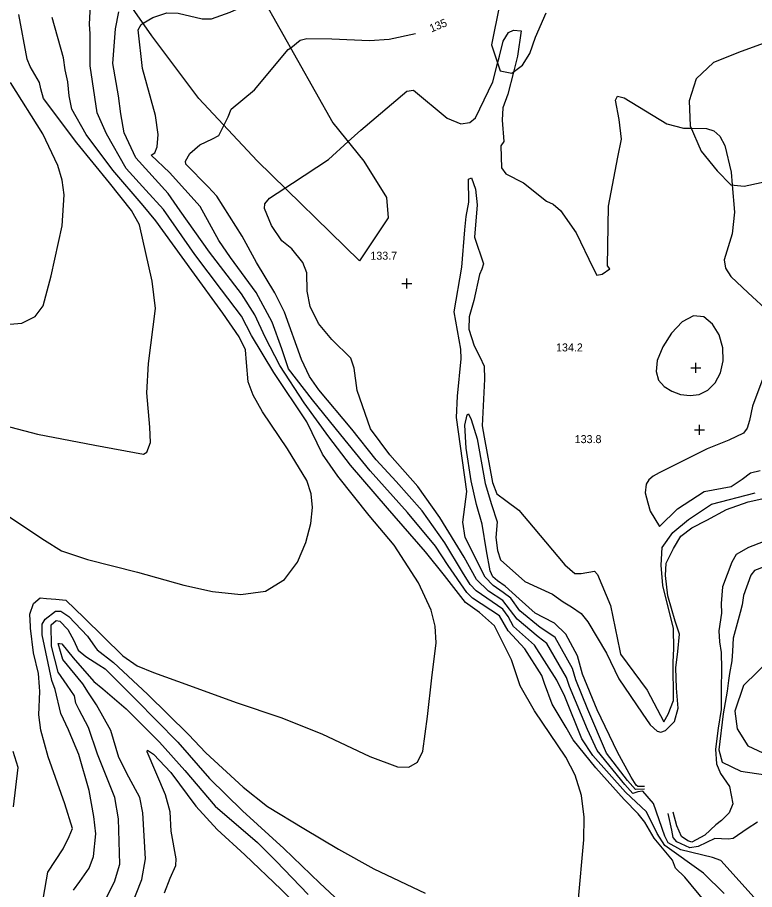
# Model space of a CAD drawing. Extents: x 1475150 to 2003689, y 770235 to 1112803.
# Drawn here: x 2000830.5 to 2001014.7, y 773169.6 to 773387.6 of the extents above; entities that cross this region are included whole.
import ezdxf

# ---------------------------------------------------------------- set-up
doc = ezdxf.new("R2010")
doc.units = 0
for name, color, linetype in [('RD_DTM_Major1', 7, 'Continuous'), ('RD_DTM_Major1_Lbl', 7, 'Continuous'), ('RD_DTM_Major2', 7, 'Continuous'), ('RD_DTM_Minor1', 7, 'Continuous'), ('RD_DTM_Minor2', 7, 'Continuous'), ('RD_DTM_Obscure', 7, 'Continuous'), ('RD_DTM_Spot_Elev', 7, 'Continuous')]:
    doc.layers.add(name, color=color, linetype=linetype)

msp = doc.modelspace()

# ---------------------------------------------------------------- linework, layer by layer
at = {"layer": 'RD_DTM_Major1'}
for points in [[(2000823.61, 773286.56), (2000835.44, 773283.45), (2000849.78, 773280.65), (2000861.94, 773278.4), (2000862.84, 773278.97), (2000863.74, 773281.34), (2000863.57, 773285.19), (2000862.8, 773293.75), (2000863.21, 773301.08), (2000864.95, 773314.89), (2000864.13, 773321.67), (2000861.01, 773335.77), (2000858.98, 773339.39), (2000853.45, 773346.24), (2000845.35, 773356.26), (2000837.01, 773367.33), (2000836.27, 773369.74), (2000836, 773371.36), (2000833.61, 773375.31), (2000832.9, 773377.17), (2000830.83, 773388.35)], [(2000898.77, 773380.04), (2000901.12, 773381.94), (2000902.79, 773382.31), (2000909.07, 773382.25), (2000918.51, 773381.88), (2000923.39, 773382.14), (2000929.97, 773383.62)], [(2001007.11, 773168.58), (2001001.96, 773173.74), (2000992.33, 773180.61), (2000990.39, 773183.64), (2000987.75, 773189.06), (2000982.44, 773193.96), (2000974.3, 773203.14), (2000971.57, 773207.31), (2000967.29, 773217.86), (2000965.29, 773221.91), (2000959.7, 773230.67), (2000954.49, 773235.36), (2000953.17, 773237.9), (2000951.82, 773239.71), (2000945.11, 773244.26), (2000943.67, 773245.83), (2000941.74, 773248.92), (2000937.29, 773256.3), (2000931.61, 773264.29), (2000925.11, 773271.64), (2000920.11, 773277.05), (2000914.03, 773284.7), (2000905.83, 773294.52), (2000903.5, 773297.85), (2000901.49, 773302.08), (2000897.23, 773313.94), (2000894.85, 773318.79), (2000890.21, 773326.36), (2000886.63, 773332.92), (2000880.33, 773342.97), (2000878.17, 773345.3), (2000872.59, 773350.92), (2000872.47, 773351.65), (2000873.6, 773353.57), (2000876.03, 773355.75), (2000879.2, 773357.29), (2000880.82, 773358.06), (2000882.1, 773360.61)], [(2000858.92, 773165.4), (2000861.54, 773172.12), (2000862.46, 773177.26), (2000861.8, 773188.76), (2000861.02, 773192.62), (2000858.28, 773197.67), (2000855.8, 773202.65), (2000853.78, 773209.38), (2000850.21, 773215.8), (2000848.25, 773218.77), (2000846.78, 773220.99), (2000841.81, 773227.11), (2000840.62, 773231.12), (2000840.96, 773231.09), (2000841.55, 773231.06), (2000844.37, 773227.53), (2000849.57, 773221.61), (2000851.85, 773219.77), (2000857.63, 773214.81), (2000866, 773206.47), (2000872.28, 773199.4), (2000879.86, 773190.48), (2000890.44, 773181.38), (2000895.17, 773176.72), (2000903.11, 773168.36)]]:
    msp.add_lwpolyline(points, dxfattribs=at)
at = {"layer": 'RD_DTM_Major2'}
msp.add_lwpolyline([(2000882.1, 773360.61), (2000883.18, 773362.75), (2000883.92, 773364.66), (2000889.7, 773369.5), (2000898.18, 773379.57), (2000898.77, 773380.04)], dxfattribs=at)
at = {"layer": 'RD_DTM_Minor1'}
for points in [[(2000835.89, 773161.45), (2000838.06, 773173.95), (2000841.91, 773179.77), (2000843.41, 773182.86), (2000844.21, 773184.91), (2000842.31, 773191), (2000838.17, 773202.81), (2000836.27, 773209.45), (2000835.8, 773213.25), (2000836.04, 773219.12), (2000835.96, 773220.31), (2000835.73, 773223.6), (2000834.51, 773228.8), (2000833.74, 773234.97), (2000833.69, 773235.38), (2000833.56, 773238.41), (2000834.49, 773241.12), (2000836.15, 773242.55), (2000837.71, 773242.37), (2000840.08, 773242.22), (2000842.54, 773241.91), (2000847.17, 773237.56), (2000856.82, 773228.02), (2000860.37, 773225.57), (2000864.47, 773223.86), (2000873.44, 773220.6), (2000885.12, 773216.39), (2000896.32, 773212.63), (2000906.6, 773208.57), (2000918.52, 773202.83), (2000925.47, 773200.25), (2000928.34, 773200.18), (2000930.5, 773201.42), (2000931.83, 773204.2), (2000932.96, 773212.87), (2000934.05, 773222.5), (2000935.12, 773231.27), (2000934.92, 773235.42), (2000933.92, 773239.43), (2000930.7, 773246.29), (2000924.64, 773255.67), (2000918.42, 773263.14), (2000910.57, 773272.92), (2000906.73, 773278.42), (2000902.84, 773286.5), (2000894.59, 773298.83), (2000888.95, 773308.13), (2000886.48, 773312.92), (2000881.5, 773319.56), (2000874.82, 773328.37), (2000866.95, 773339.58), (2000862.6, 773344.42), (2000857.65, 773349.82), (2000852.7, 773358.52), (2000850.42, 773363.76), (2000848.61, 773375.52), (2000848.65, 773383.49), (2000848.47, 773385.92), (2000848.73, 773390.67)], [(2000826.59, 773264.05), (2000837.22, 773256.95), (2000841.51, 773254.25), (2000848.01, 773252.15), (2000860.47, 773248.98), (2000872.06, 773245.73), (2000879.22, 773244.11), (2000886.3, 773243.38), (2000892.51, 773244.22), (2000897.21, 773247.09), (2000900.49, 773251.41), (2000902.59, 773256.36), (2000903.77, 773261.14), (2000904.22, 773265.12), (2000903.92, 773268.55), (2000902.81, 773271.87), (2000898.01, 773279.81), (2000891.74, 773289.06), (2000889.38, 773293.2), (2000888.12, 773296.56), (2000887.71, 773301.32), (2000887.5, 773304.54), (2000885.86, 773307.75), (2000881.85, 773313.71), (2000874.05, 773324.35), (2000865.09, 773336.78), (2000861.91, 773340.56), (2000854.3, 773349.44), (2000847.65, 773358.36), (2000844.1, 773364.68), (2000843.39, 773368.05), (2000843.07, 773371.53), (2000842.38, 773374.53), (2000841.94, 773377.53), (2000839.16, 773387.63)], [(2000970.62, 773166.4), (2000972.09, 773182.07), (2000972.16, 773187.7), (2000971.49, 773193.14), (2000969.86, 773198.17), (2000967.57, 773202.69), (2000959.7, 773214.29), (2000956.14, 773220.49), (2000953.98, 773227.07), (2000949.72, 773235.53), (2000945.98, 773238.9), (2000942.51, 773241.37), (2000937.22, 773248.09), (2000932.51, 773254.05), (2000923, 773264.92), (2000913.71, 773275.65), (2000908.27, 773282.81), (2000902.16, 773291.29), (2000896.09, 773300.57), (2000892.43, 773307.72), (2000889.83, 773313.3), (2000886.51, 773318.51), (2000878.51, 773328.92), (2000871.17, 773339.24), (2000868.13, 773343.6), (2000860.07, 773352.52), (2000857.17, 773358.73), (2000856.34, 773363.48), (2000855.73, 773368.01), (2000854.28, 773376.12), (2000854.97, 773384.73), (2000855.81, 773389.03)], [(2001007.61, 773160.19), (2000997.3, 773172.67), (2000994.95, 773174.96), (2000994.19, 773176.99), (2000989.63, 773182.48), (2000987.31, 773186.44), (2000985.66, 773188.52), (2000982.13, 773192.14), (2000975.07, 773200.04), (2000969.35, 773207.06), (2000967.6, 773210.12), (2000964.17, 773215.91), (2000962.26, 773221.09), (2000961.53, 773223.14), (2000957.27, 773229.81), (2000953.1, 773234.27), (2000951.01, 773238.07), (2000944.2, 773242.45), (2000942.82, 773243.9), (2000938.16, 773250.64), (2000934.94, 773255.43), (2000928.01, 773263.88), (2000918.62, 773274.26), (2000911.31, 773283.26), (2000904.24, 773292.01), (2000898.25, 773299.77), (2000896.58, 773304.78), (2000894.12, 773311.43), (2000890.11, 773318.89), (2000883.75, 773327.64), (2000880.83, 773331.83), (2000876.14, 773340.37), (2000868.44, 773348.87), (2000863.92, 773353.17), (2000864.79, 773353.74), (2000865.43, 773355.3), (2000865.67, 773358.37), (2000864.94, 773363.06), (2000861.7, 773374.85), (2000860.62, 773384.49), (2000861.41, 773385.87), (2000861.92, 773386.16)], [(2000913.14, 773356.58), (2000916.29, 773359.44), (2000927.84, 773369.15), (2000929.46, 773369.45), (2000937.86, 773362.44), (2000941.29, 773360.98), (2000943.55, 773361.32), (2000944.99, 773362.54), (2000949.32, 773371.55), (2000950.51, 773376.09)], [(2000954.44, 773373.93), (2000953.04, 773368.43), (2000951.84, 773364.99), (2000951.68, 773361.9), (2000952.02, 773356.56), (2000951.31, 773355.48), (2000951.46, 773350.01), (2000952.54, 773348.51), (2000956.98, 773346.3), (2000962.7, 773341.69), (2000964.38, 773340.93), (2000966.24, 773339.38), (2000970.1, 773333.74), (2000974.4, 773324.95), (2000975.32, 773323.19), (2000976.63, 773323.42), (2000978.53, 773324.77), (2000977.99, 773325.52), (2000978.22, 773340.42), (2000980.53, 773352.66), (2000981.49, 773357.22), (2000980.87, 773362.1), (2000979.95, 773366.89), (2000980.48, 773367.94), (2000982.13, 773367.54), (2000992.83, 773361.02), (2000996.94, 773359.95), (2000998.9, 773359.93)], [(2000826.59, 773310.79), (2000831.54, 773311.18), (2000834.86, 773312.82), (2000836.86, 773315.53), (2000838.91, 773322.98), (2000841.64, 773335.52), (2000842.13, 773343.3), (2000841.61, 773346.95), (2000840.56, 773350.62), (2000836.82, 773358.51), (2000828.75, 773371.32)], [(2000987.21, 773194.73), (2000984.99, 773194.59), (2000982.96, 773196.88), (2000977.74, 773203.73), (2000973.07, 773214.58), (2000970.08, 773222.05), (2000969.19, 773224.9), (2000964.89, 773232.62), (2000963.3, 773233.72), (2000961.14, 773235.13), (2000956.03, 773239.25), (2000953.77, 773242.44), (2000951.85, 773243.88), (2000949.39, 773245.57), (2000947.42, 773247.72), (2000942.41, 773257.59), (2000941.79, 773261.43), (2000942.78, 773269.14), (2000941.74, 773276.88), (2000940.21, 773287.64), (2000940.47, 773292.95), (2000941.4, 773302.27), (2000941.28, 773304.71), (2000939.68, 773314), (2000941.56, 773325.16), (2000942.27, 773334.55), (2000942.61, 773337.83), (2000943.31, 773341.45), (2000943.26, 773347.15), (2000944.01, 773347.51), (2000944.96, 773344.66), (2000945.39, 773340.77), (2000944.69, 773332.69), (2000946.98, 773326.02), (2000946.57, 773324.68), (2000945.96, 773323.36), (2000944.56, 773316.89), (2000943.36, 773312.79), (2000943.34, 773309.72), (2000944.65, 773305.51), (2000946.08, 773302.79), (2000947.18, 773300.41), (2000947.23, 773297.18), (2000946.65, 773285.56), (2000947.18, 773282.73), (2000949.2, 773271.35), (2000950.32, 773268.54), (2000952.57, 773266.9), (2000955.8, 773264.47), (2000959.41, 773260.2), (2000967.3, 773250.79), (2000969.79, 773248.63), (2000971.42, 773248.61), (2000974.69, 773249.2), (2000975.48, 773248.35), (2000978.69, 773240.64), (2000981.02, 773229.29), (2000981.2, 773228.48), (2000987.88, 773219.42), (2000992.05, 773211.51), (2000993.18, 773213.49), (2000994.48, 773216.86), (2000994.35, 773226.53), (2000994.59, 773229.81), (2000994.49, 773234.83), (2000991.77, 773245.59), (2000991.35, 773250.72), (2000991.68, 773255.12), (2000994.29, 773258.89), (2000998.25, 773262.15), (2001003.94, 773265.92), (2001014.9, 773268.8)], [(2001014.65, 773167.6), (2001006.28, 773176.87), (2001004.23, 773177.61), (2000996.28, 773179.53), (2000993.12, 773181.3), (2000992.34, 773182.97), (2000989.5, 773191.09), (2000986.82, 773194.24), (2000985.55, 773194.02), (2000984.29, 773193.61), (2000982.29, 773195.84), (2000975.38, 773204.38), (2000972.94, 773209.6), (2000968.49, 773220.37), (2000967.69, 773222.63), (2000962.79, 773231.08), (2000960.6, 773232.8), (2000955.37, 773237.19), (2000951.77, 773241.85), (2000948.24, 773244.16), (2000945.26, 773247.09), (2000942.16, 773252.73), (2000936.05, 773262.58), (2000930.59, 773270.37), (2000923.58, 773278.27), (2000918.71, 773284.74), (2000915.43, 773294.39), (2000914.66, 773299.94), (2000913.77, 773302.46), (2000909.03, 773307.11), (2000905.72, 773311.07), (2000903.64, 773315.34), (2000902.93, 773319.18), (2000902.84, 773323.76), (2000901.8, 773326.36), (2000899.07, 773329.76), (2000896.57, 773331.77), (2000893.96, 773335.62), (2000892.2, 773339.86), (2000892.29, 773340.98), (2000893.51, 773342.43), (2000897.35, 773344.97)], [(2001009.15, 773345.73), (2001009.75, 773338.9), (2001009.13, 773333.54), (2001007.14, 773326.98), (2001007.46, 773324.93), (2001008.77, 773322.83), (2001013.1, 773318.77), (2001018.38, 773313.94)], [(2001003.07, 773294.42), (2001004.87, 773296.28), (2001006.19, 773298.8), (2001006.89, 773301.79), (2001006.82, 773305.01), (2001005.91, 773308.23), (2001004.26, 773310.97), (2001002.05, 773312.74), (2000999.45, 773313.02), (2000996.65, 773311.51), (2000993.98, 773308.7), (2000991.77, 773305.25), (2000990.4, 773301.86), (2000990.1, 773299.08), (2000990.75, 773296.93), (2000992.14, 773295.33), (2000994.05, 773294.16), (2000996.26, 773293.38), (2000998.6, 773293.07), (2001000.93, 773293.37), (2001003.07, 773294.42)], [(2001017.04, 773298.06), (2001014.25, 773290.44), (2001013.46, 773286.87), (2001012.92, 773284.91), (2001011.99, 773283.67), (2001008.27, 773281.96), (2001002.85, 773279.77), (2000990.89, 773273.75), (2000989.38, 773272.98), (2000988.3, 773272.05), (2000987.68, 773270.97), (2000987.42, 773268.81), (2000988.03, 773266.26), (2000988.64, 773264.17), (2000991, 773260.32), (2000995.45, 773264.77), (2001002.1, 773269.13), (2001008.85, 773270.34), (2001011.68, 773272.21), (2001013.69, 773273.76), (2001016.17, 773274.38)], [(2000987.19, 773195.4), (2000985.52, 773195.35), (2000985.12, 773195.68), (2000983.88, 773197.74), (2000980.49, 773203.91), (2000975.4, 773214.55), (2000971.74, 773223.48), (2000970.46, 773228.05), (2000967.52, 773233.47), (2000964.7, 773236.2), (2000961.94, 773237.59), (2000959.92, 773238.7), (2000955.93, 773242.29), (2000952.37, 773245.42), (2000950.51, 773246.81), (2000949.27, 773247.74), (2000948.65, 773249.29), (2000947.72, 773254.24), (2000946.64, 773260.93), (2000945.25, 773265.86), (2000943.85, 773271.74), (2000942.61, 773279.95), (2000942.3, 773285.68), (2000942.85, 773288.29), (2000943.25, 773288.56), (2000943.85, 773287.07), (2000945.4, 773282.27), (2000947.41, 773271.12), (2000948.96, 773265.86), (2000950.36, 773261.52), (2000950.05, 773257.65), (2000950.51, 773254.4), (2000951.23, 773252.01), (2000957.27, 773246.61), (2000960.38, 773245.18), (2000964.2, 773243.48), (2000965.72, 773242.33), (2000966.89, 773241.51), (2000968.99, 773240.3), (2000971.35, 773238.59), (2000973.03, 773236.56), (2000977.71, 773228.71), (2000980.79, 773222.28), (2000986.64, 773213.73), (2000988.68, 773210.82), (2000990.39, 773209.23), (2000991.34, 773208.96), (2000992.48, 773209.38), (2000994.76, 773211.62), (2000995.67, 773214.94), (2000995.24, 773219.93), (2000995.02, 773224.99), (2000995.52, 773229.13), (2000995.95, 773233.48), (2000994.88, 773236.69), (2000993.03, 773243.03), (2000992.46, 773248.1), (2000992.67, 773251.16), (2000994.45, 773254.87), (2000996.31, 773257.94), (2000999.09, 773260), (2001002.8, 773261.93), (2001007.72, 773264.64), (2001013.14, 773266.49), (2001020.27, 773268.13)], [(2001016.92, 773256.51), (2001013.23, 773255.09), (2001010.15, 773253.34), (2001009.03, 773251.44), (2001006.7, 773245.29), (2001006.43, 773241.15), (2001006.51, 773238.68), (2001005.83, 773234.32), (2001006, 773231.56), (2001006.38, 773228.83), (2001006.48, 773224.82), (2001006.43, 773219.64), (2001006.36, 773214.58), (2001005.65, 773209.95), (2001004.94, 773204.74), (2001005.22, 773201.03), (2001006.22, 773198.61), (2001008.51, 773195.39), (2001009.32, 773191.07), (2001008.37, 773188.77), (2001006.46, 773186.86), (2001005.08, 773185.78), (2001002.28, 773183.2), (2000999.09, 773181.48), (2000998.09, 773181.75), (2000996.46, 773182.91), (2000995.3, 773185.55), (2000994.43, 773188.94)], [(2001021.96, 773252.11), (2001014.7, 773249.39), (2001013.83, 773248.2), (2001011.98, 773243.1), (2001011.6, 773240.8), (2001011.13, 773238.88), (2001009.37, 773232.44), (2001009.22, 773229.23), (2001009.04, 773226.79), (2001008.44, 773223.61), (2001008.24, 773221.9), (2001007.91, 773219.16), (2001006.86, 773213.56), (2001005.81, 773204.57), (2001006.65, 773201.41), (2001011.33, 773199.17), (2001017.49, 773198.26)], [(2000844.49, 773169.47), (2000846.02, 773171.61), (2000848.39, 773174.92), (2000849.5, 773177.9), (2000850.09, 773183.55), (2000849.54, 773187.89), (2000848.39, 773194.33), (2000845.8, 773203.35), (2000843.4, 773209.1), (2000843.2, 773209.54), (2000841.29, 773213.62), (2000839.92, 773219.59), (2000839.05, 773221.85), (2000836.65, 773233.26), (2000836.67, 773235.94), (2000837.4, 773237.18), (2000839.99, 773239.17), (2000841.3, 773239.23), (2000843.32, 773237.84), (2000848, 773232.94), (2000849.92, 773230.2), (2000850.37, 773229.57), (2000854.49, 773226.36), (2000862.97, 773218.48), (2000873.19, 773208.36), (2000877.54, 773203.81), (2000886.86, 773195.18), (2000892.94, 773190.35), (2000902.03, 773184.9), (2000910.71, 773179.67), (2000919.52, 773174.8), (2000932.39, 773168.72)], [(2000851.53, 773165.3), (2000854.72, 773171.56), (2000856.05, 773175.92), (2000855.74, 773187.25), (2000854.77, 773192.6), (2000850.51, 773203.48), (2000848.22, 773210.1), (2000845.93, 773214.52), (2000845.05, 773216.22), (2000844.76, 773218.07), (2000842.92, 773220.67), (2000840.65, 773223.98), (2000839, 773230.41), (2000838.92, 773235.8), (2000840.15, 773236.86), (2000841.04, 773236.68), (2000843.08, 773234.61), (2000844.6, 773231.9), (2000845.63, 773229.48), (2000847.56, 773227.85), (2000850.82, 773225.8), (2000852.39, 773224.81), (2000860.03, 773217.11), (2000870.54, 773206.41), (2000878.44, 773197.34), (2000886.72, 773189.25), (2000897.04, 773179.9), (2000906.02, 773171.21), (2000914.71, 773163.12)], [(2000867.25, 773168.77), (2000868.66, 773172.43), (2000870.09, 773175.59), (2000870.18, 773177.32), (2000868.86, 773184.2), (2000868.61, 773189.03), (2000867.48, 773193.25), (2000862.92, 773204.07), (2000863.01, 773204.46), (2000864.51, 773203.43), (2000868.78, 773198.83), (2000875.1, 773190.49), (2000880.36, 773184.66), (2000887.33, 773178.25), (2000896.37, 773169.65), (2000906.34, 773159.89)], [(2000829.44, 773190.32), (2000830.68, 773200.15), (2000829.38, 773204.12)], [(2001015.47, 773186.48), (2001012.89, 773184.8), (2001009.42, 773182.37), (2001008.17, 773182.17), (2001004.83, 773182.38), (2001002.75, 773181.38), (2001000.67, 773180.38), (2000998.57, 773180.06), (2000995.29, 773181.57), (2000994.35, 773182.63), (2000994.03, 773184.45), (2000993.17, 773188.62)]]:
    msp.add_lwpolyline(points, dxfattribs=at)
at = {"layer": 'RD_DTM_Minor2'}
for points in [[(2000861.92, 773386.16), (2000864.34, 773387.58), (2000867.83, 773388.78), (2000870.65, 773388.67), (2000876.64, 773387.22), (2000878.94, 773387.25), (2000883.67, 773388.93), (2000888.33, 773391.05), (2000892.16, 773391.76)], [(2000950.51, 773376.09), (2000950.99, 773377.93), (2000951.92, 773381.7), (2000953.22, 773383.87), (2000954.5, 773384.42), (2000956.36, 773384.26), (2000955.47, 773377.97), (2000954.44, 773373.93)], [(2000998.9, 773359.93), (2001002.74, 773359.88), (2001004.54, 773359.3), (2001006.09, 773357.94), (2001007.3, 773355.57), (2001008.87, 773348.91), (2001009.15, 773345.73)], [(2000897.35, 773344.97), (2000899.21, 773346.19), (2000908.21, 773352.12), (2000913.14, 773356.58)]]:
    msp.add_lwpolyline(points, dxfattribs=at)
at = {"layer": 'RD_DTM_Obscure'}
for points in [[(2000770.7, 773535.19), (2000787.27, 773514.02), (2000805.49, 773490.1), (2000823.32, 773468.94), (2000837.91, 773452.39), (2000860.86, 773428.21), (2000887.24, 773400.47), (2000909.35, 773361.29), (2000917.09, 773351.66), (2000922.72, 773342.58), (2000923.12, 773337.49), (2000915.94, 773326.73)], [(2000915.94, 773326.73), (2000890.4, 773351.79), (2000875.77, 773367.34), (2000864.07, 773383.05), (2000855.01, 773396.12), (2000845.08, 773409.36), (2000833.89, 773423.86), (2000822.15, 773437.52), (2000804.67, 773457.85), (2000795.18, 773467.83), (2000788.76, 773473.19), (2000781.06, 773480.88), (2000772.5, 773491.47), (2000764.89, 773501.6), (2000758.24, 773509.11), (2000749.85, 773518.03), (2000739.78, 773531.64)], [(2000950.97, 773390.69), (2000949, 773380.73), (2000951.1, 773374.28), (2000954.08, 773373.66), (2000956.72, 773375.66), (2000958.56, 773378.6), (2000959.99, 773382.64), (2000962.64, 773388.74)], [(2001019.01, 773381.81), (2001011.39, 773379.06), (2001004.45, 773376.37), (2001000.13, 773372.3), (2000998.35, 773366.77), (2000998.66, 773360.5), (2001001.4, 773354.14), (2001005.42, 773349.25), (2001008.78, 773345.77), (2001012.17, 773345.42), (2001029.93, 773349.25)], [(2001022.28, 773230.73), (2001011.96, 773220.58), (2001009.82, 773214.21), (2001010.36, 773209.78), (2001013.07, 773205.57), (2001021.64, 773201.51)]]:
    msp.add_lwpolyline(points, dxfattribs=at)
at = {"layer": 'RD_DTM_Spot_Elev'}
for p, q in [((2000927.83, 773319.82), (2000927.83, 773322.32)), ((2000926.58, 773321.07), (2000929.08, 773321.07)), ((2001000.05, 773298.79), (2001000.05, 773301.29)), ((2000998.8, 773300.04), (2001001.3, 773300.04)), ((2001000.98, 773283.3), (2001000.98, 773285.8)), ((2000999.73, 773284.55), (2001002.23, 773284.55))]:
    msp.add_line(p, q, dxfattribs=at)

# ---------------------------------------------------------------- texts
at = {"layer": 'RD_DTM_Major1_Lbl'}
msp.add_text('135', height=2, rotation=22.426, dxfattribs=at).set_placement((2000933.95, 773383.84))
at = {"layer": 'RD_DTM_Spot_Elev'}
for s, p in [('133.7', (2000918.69, 773327.05)), ('134.2', (2000965.11, 773304.12)), ('133.8', (2000969.77, 773281.2))]:
    msp.add_text(s, height=2, dxfattribs=at).set_placement(p)

doc.saveas('drawing.dxf')
